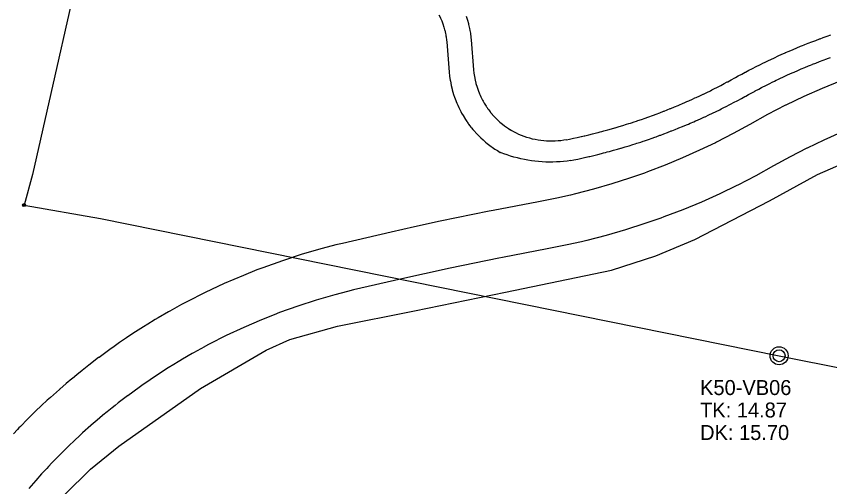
# Model space of a CAD drawing. Extents: x 702630 to 703245, y 6205279 to 6205714.
# Drawn here: x 702766.1 to 702969.7, y 6205441.3 to 6205559 of the extents above; entities that cross this region are included whole.
import ezdxf

# ---------------------------------------------------------------- set-up
doc = ezdxf.new("R2010")
doc.units = 0
for name, color, linetype in [('Brønd', 7, 'Continuous'), ('Brønd_Text', 7, 'Continuous'), ('Dæksel', 7, 'Continuous'), ('Matrikelskel Almindeligt', 7, 'Continuous'), ('Optaget vej', 7, 'Continuous'), ('Punkt', 7, 'Continuous'), ('Trykledning', 7, 'Continuous')]:
    doc.layers.add(name, color=color, linetype=linetype)

msp = doc.modelspace()

# ---------------------------------------------------------------- linework, layer by layer
at = {"layer": 'Brønd'}
msp.add_line((702957.06, 6205474.08), (702957.06, 6205474.08), dxfattribs=at)
msp.add_circle((702957.06, 6205474.08), 2.25, dxfattribs=at)
at = {"layer": 'Dæksel'}
msp.add_line((702957.06, 6205474.08), (702957.06, 6205474.08), dxfattribs=at)
msp.add_circle((702957.06, 6205474.08), 1.5, dxfattribs=at)
at = {"layer": 'Matrikelskel Almindeligt'}
for p, q in [((702966.64, 6205519.43), (702982.18, 6205526.16)), ((702954.65, 6205512.84), (702966.64, 6205519.43)), ((702935.98, 6205503.15), (702954.65, 6205512.84)), ((702926.22, 6205499.06), (702935.98, 6205503.15)), ((702915.08, 6205495.48), (702926.22, 6205499.06)), ((702888.58, 6205489.98), (702915.08, 6205495.48)), ((702865.75, 6205485.31), (702888.58, 6205489.98)), ((702846.51, 6205481.51), (702865.75, 6205485.31)), ((702834.55, 6205478.14), (702846.51, 6205481.51)), ((702828.63, 6205475.49), (702834.55, 6205478.14)), ((702812.2, 6205465.9), (702828.63, 6205475.49)), ((702791.81, 6205451.44), (702812.2, 6205465.9)), ((702784.67, 6205445.7), (702791.81, 6205451.44)), ((702778.15, 6205439.27), (702784.67, 6205445.7))]:
    msp.add_line(p, q, dxfattribs=at)
at = {"layer": 'Optaget vej'}
for points in [[(702871.91, 6205559.42), (702872.27, 6205558.66), (702872.31, 6205558.58), (702872.6, 6205557.9), (702872.88, 6205557.14), (702872.89, 6205557.11), (702873.15, 6205556.32), (702873.33, 6205555.65), (702873.37, 6205555.51), (702873.55, 6205554.69), (702873.62, 6205554.34), (702873.65, 6205554.14), (702873.7, 6205553.87), (702873.81, 6205553.04), (702873.85, 6205552.6), (702874.47, 6205545.07), (702874.59, 6205544.01), (702874.74, 6205542.93), (702874.76, 6205542.86), (702874.98, 6205541.72), (702875.19, 6205540.82), (702875.25, 6205540.58), (702875.58, 6205539.47), (702875.82, 6205538.75), (702875.96, 6205538.37), (702876.38, 6205537.28), (702876.62, 6205536.74), (702876.86, 6205536.22), (702877.38, 6205535.18), (702877.58, 6205534.81), (702877.95, 6205534.17), (702878.56, 6205533.18), (702878.7, 6205532.97), (702878.9, 6205532.68), (702879.03, 6205532.5), (702879.09, 6205532.4), (702879.22, 6205532.22), (702879.34, 6205532.05), (702879.67, 6205531.62), (702879.92, 6205531.29), (702879.98, 6205531.22), (702880.07, 6205531.11), (702880.41, 6205530.7), (702880.59, 6205530.49), (702880.67, 6205530.4), (702881.39, 6205529.6), (702881.45, 6205529.54), (702882.27, 6205528.71), (702882.37, 6205528.62), (702882.94, 6205528.09), (702883.13, 6205527.92), (702883.55, 6205527.56), (702884.02, 6205527.18), (702884.61, 6205526.72), (702884.95, 6205526.47), (702885.27, 6205526.25), (702885.91, 6205525.81), (702886.39, 6205525.5), (702886.53, 6205525.42), (702886.89, 6205525.19), (702887.27, 6205524.97), (702887.28, 6205524.97)], [(702878.71, 6205559.06), (702879.03, 6205558.08), (702879.27, 6205557.23), (702879.34, 6205556.93), (702879.57, 6205555.94), (702879.66, 6205555.44), (702879.71, 6205555.16), (702879.77, 6205554.76), (702879.91, 6205553.73), (702879.96, 6205553.15), (702880.59, 6205545.64), (702880.68, 6205544.77), (702880.8, 6205543.93), (702880.98, 6205543.02), (702881.15, 6205542.31), (702881.17, 6205542.22), (702881.44, 6205541.3), (702881.62, 6205540.76), (702881.7, 6205540.53), (702882.06, 6205539.63), (702882.22, 6205539.25), (702882.39, 6205538.88), (702882.82, 6205538.02), (702882.95, 6205537.8), (702883.22, 6205537.31), (702883.73, 6205536.5), (702883.81, 6205536.38), (702883.96, 6205536.16), (702884.06, 6205536.01), (702884.1, 6205535.96), (702884.2, 6205535.81), (702884.28, 6205535.7), (702884.54, 6205535.35), (702884.75, 6205535.09), (702884.78, 6205535.06), (702884.84, 6205534.98), (702885.11, 6205534.64), (702885.25, 6205534.49), (702885.27, 6205534.47), (702885.87, 6205533.8), (702886.57, 6205533.1), (702887.06, 6205532.65), (702887.16, 6205532.56), (702887.49, 6205532.27), (702887.85, 6205531.99), (702888.32, 6205531.62), (702888.56, 6205531.44), (702888.78, 6205531.29), (702889.3, 6205530.94), (702889.68, 6205530.69), (702889.74, 6205530.65), (702890.03, 6205530.47)], [(702903.85, 6205528.12), (702903.86, 6205528.13), (702904.61, 6205528.28), (702905.58, 6205528.48), (702906.54, 6205528.69), (702907.5, 6205528.91), (702907.6, 6205528.93), (702908.27, 6205529.09), (702908.45, 6205529.13), (702909.41, 6205529.36), (702910.36, 6205529.59), (702911.32, 6205529.84), (702911.8, 6205529.96), (702912.27, 6205530.08), (702912.66, 6205530.19), (702913.22, 6205530.34), (702914.17, 6205530.6), (702915.11, 6205530.87), (702915.97, 6205531.11), (702916.05, 6205531.14), (702917, 6205531.42), (702917.01, 6205531.42), (702917.94, 6205531.7), (702918.88, 6205532), (702919.42, 6205532.17), (702919.82, 6205532.29), (702920.1, 6205532.39), (702920.75, 6205532.6), (702921.33, 6205532.79), (702921.68, 6205532.91), (702922.61, 6205533.22), (702923.55, 6205533.55), (702924.21, 6205533.78), (702924.46, 6205533.88), (702925.4, 6205534.21), (702925.59, 6205534.29), (702926.31, 6205534.55), (702927.24, 6205534.9), (702928.16, 6205535.26), (702928.27, 6205535.3), (702929.07, 6205535.62), (702929.83, 6205535.92), (702929.97, 6205535.98), (702930.89, 6205536.35), (702931.8, 6205536.73), (702932.3, 6205536.94), (702932.7, 6205537.11), (702933.61, 6205537.51), (702933.99, 6205537.67), (702934.5, 6205537.9), (702935.41, 6205538.3), (702936, 6205538.58), (702936.28, 6205538.7), (702936.29, 6205538.71), (702937.2, 6205539.13), (702937.21, 6205539.13), (702938.08, 6205539.55), (702938.1, 6205539.56), (702938.96, 6205539.97), (702939.85, 6205540.4), (702940.2, 6205540.58), (702940.72, 6205540.84), (702941.61, 6205541.29), (702942.17, 6205541.57), (702942.48, 6205541.73), (702943.35, 6205542.19), (702944.08, 6205542.58), (702944.21, 6205542.65), (702945.08, 6205543.12), (702945.95, 6205543.59), (702946.16, 6205543.71), (702946.83, 6205544.08), (702947.72, 6205544.56), (702948.54, 6205545), (702948.63, 6205545.04), (702949.52, 6205545.51), (702950.26, 6205545.9), (702950.43, 6205545.99), (702951.33, 6205546.45), (702952.24, 6205546.9), (702953.15, 6205547.35), (702953.44, 6205547.49), (702953.57, 6205547.55), (702954.07, 6205547.79), (702954.44, 6205547.97), (702954.99, 6205548.23), (702955.91, 6205548.66), (702956.83, 6205549.09), (702957.75, 6205549.51), (702958.41, 6205549.8), (702958.67, 6205549.91), (702958.69, 6205549.92), (702959.62, 6205550.33), (702960.55, 6205550.73), (702961.49, 6205551.12), (702962.43, 6205551.51), (702962.96, 6205551.72), (702963.37, 6205551.89), (702963.48, 6205551.93), (702964.32, 6205552.27), (702965.27, 6205552.63), (702966.22, 6205553), (702967.16, 6205553.35), (702967.31, 6205553.41), (702968.12, 6205553.7), (702968.6, 6205553.88), (702969.09, 6205554.05), (702970.04, 6205554.38)], [(702904.9, 6205522.93), (702905.69, 6205523.09), (702906.69, 6205523.3), (702907.68, 6205523.52), (702908.68, 6205523.74), (702908.79, 6205523.77), (702909.47, 6205523.93), (702909.67, 6205523.97), (702910.66, 6205524.21), (702911.65, 6205524.45), (702912.64, 6205524.7), (702913.14, 6205524.83), (702913.62, 6205524.96), (702914.02, 6205525.07), (702914.61, 6205525.22), (702915.59, 6205525.49), (702916.57, 6205525.77), (702917.45, 6205526.02), (702917.55, 6205526.05), (702918.52, 6205526.34), (702918.54, 6205526.34), (702919.5, 6205526.64), (702920.47, 6205526.94), (702921.03, 6205527.12), (702921.44, 6205527.25), (702921.74, 6205527.34), (702922.41, 6205527.56), (702923.01, 6205527.76), (702923.38, 6205527.88), (702924.34, 6205528.21), (702925.3, 6205528.55), (702925.99, 6205528.79), (702926.26, 6205528.89), (702927.22, 6205529.24), (702927.43, 6205529.31), (702928.17, 6205529.59), (702929.13, 6205529.95), (702930.08, 6205530.32), (702930.2, 6205530.37), (702931.02, 6205530.69), (702931.8, 6205531), (702931.97, 6205531.07), (702932.91, 6205531.45), (702933.85, 6205531.84), (702934.37, 6205532.06), (702934.79, 6205532.24), (702935.72, 6205532.65), (702936.13, 6205532.82), (702936.66, 6205533.06), (702937.59, 6205533.47), (702938.2, 6205533.75), (702938.49, 6205533.88), (702938.52, 6205533.9), (702939.44, 6205534.32), (702939.47, 6205534.34), (702940.36, 6205534.76), (702940.39, 6205534.78), (702941.28, 6205535.2), (702942.19, 6205535.65), (702942.56, 6205535.83), (702943.1, 6205536.1), (702944.01, 6205536.56), (702944.59, 6205536.86), (702944.92, 6205537.03), (702945.82, 6205537.5), (702946.57, 6205537.9), (702946.72, 6205537.98), (702947.62, 6205538.46), (702948.51, 6205538.95), (702948.72, 6205539.07), (702949.38, 6205539.43), (702950.24, 6205539.9), (702951.03, 6205540.32), (702951.1, 6205540.36), (702951.97, 6205540.82), (702952.69, 6205541.19), (702952.84, 6205541.27), (702953.72, 6205541.71), (702954.6, 6205542.15), (702955.48, 6205542.59), (702955.76, 6205542.72), (702955.88, 6205542.78), (702956.36, 6205543.02), (702956.72, 6205543.19), (702957.25, 6205543.44), (702958.14, 6205543.86), (702959.03, 6205544.27), (702959.92, 6205544.67), (702960.56, 6205544.95), (702960.81, 6205545.06), (702960.82, 6205545.07), (702961.72, 6205545.46), (702962.62, 6205545.85), (702963.53, 6205546.23), (702964.44, 6205546.6), (702964.95, 6205546.81), (702965.35, 6205546.97), (702965.44, 6205547.01), (702966.26, 6205547.33), (702967.17, 6205547.69), (702968.09, 6205548.04), (702969.01, 6205548.38), (702969.14, 6205548.43), (702969.93, 6205548.72)], [(702972.55, 6205542.86), (702967.86, 6205540.96), (702963.23, 6205538.92), (702958.78, 6205536.79), (702958.67, 6205536.74), (702954.16, 6205534.43), (702949.73, 6205531.98), (702945.6, 6205529.7), (702941.41, 6205527.54), (702941.11, 6205527.39), (702937.16, 6205525.49), (702932.86, 6205523.56), (702928.5, 6205521.76), (702924.1, 6205520.07), (702923.36, 6205519.8), (702919.65, 6205518.51), (702915.16, 6205517.08), (702910.62, 6205515.77), (702906.06, 6205514.58), (702904.86, 6205514.29), (702901.46, 6205513.53), (702896.84, 6205512.6), (702885.46, 6205510.42), (702884.52, 6205510.23), (702872.23, 6205507.71), (702865.77, 6205506.31), (702859.98, 6205505.03), (702847.76, 6205502.2), (702846.1, 6205501.8), (702842.7, 6205500.91), (702837.69, 6205499.47), (702832.72, 6205497.86), (702827.8, 6205496.1), (702826.33, 6205495.54), (702822.94, 6205494.19), (702818.15, 6205492.12), (702813.42, 6205489.91), (702808.77, 6205487.55), (702807.62, 6205486.94), (702807.62, 6205486.94), (702807.49, 6205486.87), (702804.58, 6205485.26), (702804.19, 6205485.04), (702801.58, 6205483.52), (702800.9, 6205483.12), (702799.99, 6205482.57), (702799.69, 6205482.39), (702797.29, 6205480.9), (702795.28, 6205479.6), (702793.73, 6205478.58), (702791.97, 6205477.38), (702790.95, 6205476.67), (702790.24, 6205476.17), (702789.88, 6205475.91), (702786.81, 6205473.67), (702786.72, 6205473.61), (702784.26, 6205471.73), (702783.44, 6205471.08), (702782.59, 6205470.41), (702781.22, 6205469.31), (702780.14, 6205468.41), (702780.02, 6205468.32), (702778.57, 6205467.09), (702776.97, 6205465.71), (702776.97, 6205465.71), (702776.95, 6205465.69), (702776.89, 6205465.65), (702776.89, 6205465.64), (702774.65, 6205463.64), (702773.87, 6205462.93), (702773.78, 6205462.85), (702772.51, 6205461.67), (702770.83, 6205460.08), (702768.9, 6205458.17), (702767.14, 6205456.39), (702766.78, 6205456.01), (702766.37, 6205455.59), (702765.39, 6205454.56)], [(702903.85, 6205528.12), (702903.14, 6205527.99), (702902.43, 6205527.89), (702901.72, 6205527.82), (702901.01, 6205527.76), (702900.29, 6205527.74), (702899.57, 6205527.74), (702898.86, 6205527.77), (702898.14, 6205527.83), (702897.43, 6205527.91), (702896.72, 6205528.01), (702896.02, 6205528.15), (702895.32, 6205528.31), (702894.63, 6205528.49), (702893.94, 6205528.7), (702893.27, 6205528.94), (702892.6, 6205529.19), (702891.94, 6205529.48), (702891.29, 6205529.79), (702890.66, 6205530.12), (702890.03, 6205530.47)], [(702972.54, 6205529.9), (702968.23, 6205528.01), (702964.09, 6205526.04), (702963.99, 6205525.98), (702959.8, 6205523.83), (702955.68, 6205521.56), (702951.26, 6205519.12), (702946.77, 6205516.8), (702946.45, 6205516.64), (702942.22, 6205514.61), (702937.61, 6205512.54), (702932.95, 6205510.61), (702928.23, 6205508.8), (702927.44, 6205508.52), (702923.46, 6205507.13), (702918.65, 6205505.59), (702913.8, 6205504.19), (702908.91, 6205502.92), (702907.62, 6205502.61), (702903.98, 6205501.79), (702899.03, 6205500.8), (702887.79, 6205498.64), (702886.86, 6205498.46), (702874.72, 6205495.97), (702868.33, 6205494.59), (702862.61, 6205493.32), (702850.54, 6205490.53), (702849, 6205490.15), (702845.85, 6205489.33), (702841.19, 6205487.99), (702836.58, 6205486.5), (702832.02, 6205484.87), (702830.66, 6205484.35), (702827.52, 6205483.09), (702823.07, 6205481.18), (702818.68, 6205479.12), (702814.36, 6205476.93), (702813.31, 6205476.37), (702813.3, 6205476.37), (702813.18, 6205476.3), (702810.48, 6205474.81), (702810.11, 6205474.6), (702807.69, 6205473.2), (702807.07, 6205472.83), (702806.22, 6205472.32), (702805.94, 6205472.15), (702803.72, 6205470.76), (702801.85, 6205469.56), (702800.42, 6205468.61), (702798.78, 6205467.5), (702797.84, 6205466.84), (702797.18, 6205466.37), (702796.85, 6205466.14), (702793.99, 6205464.06), (702793.92, 6205464), (702791.63, 6205462.26), (702790.87, 6205461.66), (702790.08, 6205461.04), (702788.81, 6205460.01), (702787.8, 6205459.18), (702787.7, 6205459.09), (702786.35, 6205457.95), (702784.87, 6205456.68), (702784.86, 6205456.67), (702784.84, 6205456.66), (702784.8, 6205456.61), (702784.79, 6205456.61), (702782.71, 6205454.76), (702781.99, 6205454.1), (702781.9, 6205454.02), (702780.72, 6205452.92), (702779.18, 6205451.45), (702777.38, 6205449.68), (702775.74, 6205448.02), (702775.41, 6205447.68), (702775.03, 6205447.28), (702774.13, 6205446.33), (702773.71, 6205445.88), (702772.43, 6205444.5), (702770.98, 6205442.89), (702769.22, 6205440.88)], [(702904.9, 6205522.93), (702904.01, 6205522.8), (702903.12, 6205522.7), (702902.22, 6205522.62), (702901.33, 6205522.56), (702900.43, 6205522.53), (702899.53, 6205522.52), (702898.63, 6205522.54), (702897.74, 6205522.58), (702896.84, 6205522.65), (702895.95, 6205522.74), (702895.06, 6205522.86), (702894.17, 6205522.99), (702893.29, 6205523.16), (702892.41, 6205523.35), (702891.54, 6205523.56), (702890.67, 6205523.79), (702889.81, 6205524.05), (702888.96, 6205524.33), (702888.12, 6205524.64), (702887.28, 6205524.97)]]:
    msp.add_lwpolyline(points, dxfattribs=at)
at = {"layer": 'Punkt'}
msp.add_line((702768.06, 6205511.77), (702768.06, 6205511.77), dxfattribs=at)
for radius in [0.375, 0.3, 0.225, 0.15, 0.075]:
    msp.add_circle((702768.06, 6205511.77), radius, dxfattribs=at)
at = {"layer": 'Trykledning'}
for points in [[(702800.04, 6205651.38), (702799.73, 6205649.98), (702770.2, 6205519.44), (702768.06, 6205511.77)], [(702768.06, 6205511.77), (702787.15, 6205508.45), (702957.06, 6205474.08)], [(702957.06, 6205474.08), (703111.36, 6205443.32)]]:
    msp.add_lwpolyline(points, dxfattribs=at)

# ---------------------------------------------------------------- texts
at = {"layer": 'Brønd_Text'}
for s, p in [('K50-VB06', (702937.28, 6205464.24)), ('TK: 14.87', (702937.28, 6205458.62)), ('DK: 15.70', (702937.28, 6205452.99))]:
    msp.add_text(s, height=3.75, dxfattribs=at).set_placement(p)

doc.saveas('drawing.dxf')
